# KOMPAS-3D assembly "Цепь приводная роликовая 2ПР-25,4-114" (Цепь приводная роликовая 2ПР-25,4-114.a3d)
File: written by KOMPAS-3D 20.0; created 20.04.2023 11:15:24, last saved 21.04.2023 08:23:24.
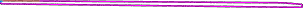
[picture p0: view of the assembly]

Document properties: Полное имя файла: C:\!WORK!\ЗИГ2-18.240.00 Линия ЗигЗаг\ЗИГ2-18.240.03.00 Цепь тяговая\Цепь приводная роликовая 2ПР-25,4-114.a3d

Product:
- Part/product: Цепь приводная роликовая 2ПР-25,4-114
    Масса: 114.772
    Раздел спецификации: Прочие изделия
  - Component [assembly]: Звено внутреннее двухрядное (25,4)  | qty 441  | pos. 627  | Масса: 0.150139; source file: ..\..\ЗИГ-18.240.00 Линия ЗигЗаг\Цепь\Звено внутренее двухрядное (25,4).a3d
  - Component [assembly]: Звено наружное двухрядное (25,4)  | qty 441  | pos. 520  | Масса: 0.110117; source file: ..\..\ЗИГ-18.240.00 Линия ЗигЗаг\Цепь\Звено наружное двухрядное (25,4).a3d

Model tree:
1. Эскиз:1
2. Массив вдоль кривой:1
3. Экземпляр ( 1 )
4. Экземпляр ( 2 )
5. Экземпляр ( 3 )
6. Экземпляр ( 4 )
7. Экземпляр ( 5 )
8. Экземпляр ( 6 )
9. Экземпляр ( 7 )
10. Экземпляр ( 8 )
11. Экземпляр ( 9 )
12. Экземпляр ( 10 )
13. Экземпляр ( 11 )
14. Экземпляр ( 12 )
15. Экземпляр ( 13 )
16. Экземпляр ( 14 )
17. Экземпляр ( 15 )
18. Экземпляр ( 16 )
19. Экземпляр ( 17 )
20. Экземпляр ( 18 )
21. Экземпляр ( 19 )
22. Экземпляр ( 20 )
23. Экземпляр ( 21 )
24. Экземпляр ( 22 )
25. Экземпляр ( 23 )
26. Экземпляр ( 24 )
27. Экземпляр ( 25 )
28. Экземпляр ( 26 )
29. Экземпляр ( 27 )
30. Экземпляр ( 28 )
31. Экземпляр ( 29 )
32. Экземпляр ( 30 )
33. Экземпляр ( 31 )
34. Экземпляр ( 32 )
35. Экземпляр ( 33 )
36. Экземпляр ( 34 )
37. Экземпляр ( 35 )
38. Экземпляр ( 36 )
39. Экземпляр ( 37 )
40. Экземпляр ( 38 )
41. Экземпляр ( 39 )
42. Экземпляр ( 40 )
43. Экземпляр ( 41 )
44. Экземпляр ( 42 )
45. Экземпляр ( 43 )
46. Экземпляр ( 44 )
47. Экземпляр ( 45 )
48. Экземпляр ( 46 )
49. Экземпляр ( 47 )
50. Экземпляр ( 48 )
51. Экземпляр ( 49 )
52. Экземпляр ( 50 )
53. Экземпляр ( 51 )
54. Экземпляр ( 52 )
55. Экземпляр ( 53 )
56. Экземпляр ( 54 )
57. Экземпляр ( 55 )
58. Экземпляр ( 56 )
59. Экземпляр ( 57 )
60. Экземпляр ( 58 )
61. Экземпляр ( 59 )
62. Экземпляр ( 60 )
63. Экземпляр ( 61 )
64. Экземпляр ( 62 )
65. Экземпляр ( 63 )
66. Экземпляр ( 64 )
67. Экземпляр ( 65 )
68. Экземпляр ( 66 )
69. Экземпляр ( 67 )
70. Экземпляр ( 68 )
71. Экземпляр ( 69 )
72. Экземпляр ( 70 )
73. Экземпляр ( 71 )
74. Экземпляр ( 72 )
75. Экземпляр ( 73 )
76. Экземпляр ( 74 )
77. Экземпляр ( 75 )
78. Экземпляр ( 76 )
79. Экземпляр ( 77 )
80. Экземпляр ( 78 )
81. Экземпляр ( 79 )
82. Экземпляр ( 80 )
83. Экземпляр ( 81 )
84. Экземпляр ( 82 )
85. Экземпляр ( 83 )
86. Экземпляр ( 84 )
87. Экземпляр ( 85 )
88. Экземпляр ( 86 )
89. Экземпляр ( 87 )
90. Экземпляр ( 88 )
91. Экземпляр ( 89 )
92. Экземпляр ( 90 )
93. Экземпляр ( 91 )
94. Экземпляр ( 92 )
95. Экземпляр ( 93 )
96. Экземпляр ( 94 )
97. Экземпляр ( 95 )
98. Экземпляр ( 96 )
99. Экземпляр ( 97 )
100. Экземпляр ( 98 )
101. Экземпляр ( 99 )
102. Экземпляр ( 100 )
103. Экземпляр ( 101 )
104. Экземпляр ( 102 )
105. Экземпляр ( 103 )
106. Экземпляр ( 104 )
107. Экземпляр ( 105 )
108. Экземпляр ( 106 )
109. Экземпляр ( 107 )
110. Экземпляр ( 108 )
111. Экземпляр ( 109 )
112. Экземпляр ( 110 )
113. Экземпляр ( 111 )
114. Экземпляр ( 112 )
115. Экземпляр ( 113 )
116. Экземпляр ( 114 )
117. Экземпляр ( 115 )
118. Экземпляр ( 116 )
119. Экземпляр ( 117 )
120. Экземпляр ( 118 )
121. Экземпляр ( 119 )
122. Экземпляр ( 120 )
123. Экземпляр ( 121 )
124. Экземпляр ( 122 )
125. Экземпляр ( 123 )
126. Экземпляр ( 124 )
127. Экземпляр ( 125 )
128. Экземпляр ( 126 )
129. Экземпляр ( 127 )
130. Экземпляр ( 128 )
131. Экземпляр ( 129 )
132. Экземпляр ( 130 )
133. Экземпляр ( 131 )
134. Экземпляр ( 132 )
135. Экземпляр ( 133 )
136. Экземпляр ( 134 )
137. Экземпляр ( 135 )
138. Экземпляр ( 136 )
139. Экземпляр ( 137 )
140. Экземпляр ( 138 )
141. Экземпляр ( 139 )
142. Экземпляр ( 140 )
143. Экземпляр ( 141 )
144. Экземпляр ( 142 )
145. Экземпляр ( 143 )
146. Экземпляр ( 144 )
147. Экземпляр ( 145 )
148. Экземпляр ( 146 )
149. Экземпляр ( 147 )
150. Экземпляр ( 148 )
151. Экземпляр ( 149 )
152. Экземпляр ( 150 )
153. Экземпляр ( 151 )
154. Экземпляр ( 152 )
155. Экземпляр ( 153 )
156. Экземпляр ( 154 )
157. Экземпляр ( 155 )
158. Экземпляр ( 156 )
159. Экземпляр ( 157 )
160. Экземпляр ( 158 )
161. Экземпляр ( 159 )
162. Экземпляр ( 160 )
163. Экземпляр ( 161 )
164. Экземпляр ( 162 )
165. Экземпляр ( 163 )
166. Экземпляр ( 164 )
167. Экземпляр ( 165 )
168. Экземпляр ( 166 )
169. Экземпляр ( 167 )
170. Экземпляр ( 168 )
171. Экземпляр ( 169 )
172. Экземпляр ( 170 )
173. Экземпляр ( 171 )
174. Экземпляр ( 172 )
175. Экземпляр ( 173 )
176. Экземпляр ( 174 )
177. Экземпляр ( 175 )
178. Экземпляр ( 176 )
179. Экземпляр ( 177 )
180. Экземпляр ( 178 )
181. Экземпляр ( 179 )
182. Экземпляр ( 180 )
183. Экземпляр ( 181 )
184. Экземпляр ( 182 )
185. Экземпляр ( 183 )
186. Экземпляр ( 184 )
187. Экземпляр ( 185 )
188. Экземпляр ( 186 )
189. Экземпляр ( 187 )
190. Экземпляр ( 188 )
191. Экземпляр ( 189 )
192. Экземпляр ( 190 )
193. Экземпляр ( 191 )
194. Экземпляр ( 192 )
195. Экземпляр ( 193 )
196. Экземпляр ( 194 )
197. Экземпляр ( 195 )
198. Экземпляр ( 196 )
199. Экземпляр ( 197 )
200. Экземпляр ( 198 )
201. Экземпляр ( 199 )
202. Экземпляр ( 200 )
203. Экземпляр ( 201 )
204. Экземпляр ( 202 )
205. Экземпляр ( 203 )
206. Экземпляр ( 204 )
207. Экземпляр ( 205 )
208. Экземпляр ( 206 )
209. Экземпляр ( 207 )
210. Экземпляр ( 208 )
211. Экземпляр ( 209 )
212. Экземпляр ( 210 )
213. Экземпляр ( 211 )
214. Экземпляр ( 212 )
215. Экземпляр ( 213 )
216. Экземпляр ( 214 )
217. Экземпляр ( 215 )
218. Экземпляр ( 216 )
219. Экземпляр ( 217 )
220. Экземпляр ( 218 )
221. Экземпляр ( 219 )
222. Экземпляр ( 220 )
223. Экземпляр ( 221 )
224. Экземпляр ( 222 )
225. Экземпляр ( 223 )
226. Экземпляр ( 224 )
227. Экземпляр ( 225 )
228. Экземпляр ( 226 )
229. Экземпляр ( 227 )
230. Экземпляр ( 228 )
231. Экземпляр ( 229 )
232. Экземпляр ( 230 )
233. Экземпляр ( 231 )
234. Экземпляр ( 232 )
235. Экземпляр ( 233 )
236. Экземпляр ( 234 )
237. Экземпляр ( 235 )
238. Экземпляр ( 236 )
239. Экземпляр ( 237 )
240. Экземпляр ( 238 )
241. Экземпляр ( 239 )
242. Экземпляр ( 240 )
243. Экземпляр ( 241 )
244. Экземпляр ( 242 )
245. Экземпляр ( 243 )
246. Экземпляр ( 244 )
247. Экземпляр ( 245 )
248. Экземпляр ( 246 )
249. Экземпляр ( 247 )
250. Экземпляр ( 248 )
251. Экземпляр ( 249 )
252. Экземпляр ( 250 )
253. Экземпляр ( 251 )
254. Экземпляр ( 252 )
255. Экземпляр ( 253 )
256. Экземпляр ( 254 )
257. Экземпляр ( 255 )
258. Экземпляр ( 256 )
259. Экземпляр ( 257 )
260. Экземпляр ( 258 )
261. Экземпляр ( 259 )
262. Экземпляр ( 260 )
263. Экземпляр ( 261 )
264. Экземпляр ( 262 )
265. Экземпляр ( 263 )
266. Экземпляр ( 264 )
267. Экземпляр ( 265 )
268. Экземпляр ( 266 )
269. Экземпляр ( 267 )
270. Экземпляр ( 268 )
271. Экземпляр ( 269 )
272. Экземпляр ( 270 )
273. Экземпляр ( 271 )
274. Экземпляр ( 272 )
275. Экземпляр ( 273 )
276. Экземпляр ( 274 )
277. Экземпляр ( 275 )
278. Экземпляр ( 276 )
279. Экземпляр ( 277 )
280. Экземпляр ( 278 )
281. Экземпляр ( 279 )
282. Экземпляр ( 280 )
283. Экземпляр ( 281 )
284. Экземпляр ( 282 )
285. Экземпляр ( 283 )
286. Экземпляр ( 284 )
287. Экземпляр ( 285 )
288. Экземпляр ( 286 )
289. Экземпляр ( 287 )
290. Экземпляр ( 288 )
291. Экземпляр ( 289 )
292. Экземпляр ( 290 )
293. Экземпляр ( 291 )
294. Экземпляр ( 292 )
295. Экземпляр ( 293 )
296. Экземпляр ( 294 )
297. Экземпляр ( 295 )
298. Экземпляр ( 296 )
299. Экземпляр ( 297 )
300. Экземпляр ( 298 )
301. Экземпляр ( 299 )
302. Экземпляр ( 300 )
303. Экземпляр ( 301 )
304. Экземпляр ( 302 )
305. Экземпляр ( 303 )
306. Экземпляр ( 304 )
307. Экземпляр ( 305 )
308. Экземпляр ( 306 )
309. Экземпляр ( 307 )
310. Экземпляр ( 308 )
311. Экземпляр ( 309 )
312. Экземпляр ( 310 )
313. Экземпляр ( 311 )
314. Экземпляр ( 312 )
315. Экземпляр ( 313 )
316. Экземпляр ( 314 )
317. Экземпляр ( 315 )
318. Экземпляр ( 316 )
319. Экземпляр ( 317 )
320. Экземпляр ( 318 )
321. Экземпляр ( 319 )
322. Экземпляр ( 320 )
323. Экземпляр ( 321 )
324. Экземпляр ( 322 )
325. Экземпляр ( 323 )
326. Экземпляр ( 324 )
327. Экземпляр ( 325 )
328. Экземпляр ( 326 )
329. Экземпляр ( 327 )
330. Экземпляр ( 328 )
331. Экземпляр ( 329 )
332. Экземпляр ( 330 )
333. Экземпляр ( 331 )
334. Экземпляр ( 332 )
335. Экземпляр ( 333 )
336. Экземпляр ( 334 )
337. Экземпляр ( 335 )
338. Экземпляр ( 336 )
339. Экземпляр ( 337 )
340. Экземпляр ( 338 )
341. Экземпляр ( 339 )
342. Экземпляр ( 340 )
343. Экземпляр ( 341 )
344. Экземпляр ( 342 )
345. Экземпляр ( 343 )
346. Экземпляр ( 344 )
347. Экземпляр ( 345 )
348. Экземпляр ( 346 )
349. Экземпляр ( 347 )
350. Экземпляр ( 348 )
351. Экземпляр ( 349 )
352. Экземпляр ( 350 )
353. Экземпляр ( 351 )
354. Экземпляр ( 352 )
355. Экземпляр ( 353 )
356. Экземпляр ( 354 )
357. Экземпляр ( 355 )
358. Экземпляр ( 356 )
359. Экземпляр ( 357 )
360. Экземпляр ( 358 )
361. Экземпляр ( 359 )
362. Экземпляр ( 360 )
363. Экземпляр ( 361 )
364. Экземпляр ( 362 )
365. Экземпляр ( 363 )
366. Экземпляр ( 364 )
367. Экземпляр ( 365 )
368. Экземпляр ( 366 )
369. Экземпляр ( 367 )
370. Экземпляр ( 368 )
371. Экземпляр ( 369 )
372. Экземпляр ( 370 )
373. Экземпляр ( 371 )
374. Экземпляр ( 372 )
375. Экземпляр ( 373 )
376. Экземпляр ( 374 )
377. Экземпляр ( 375 )
378. Экземпляр ( 376 )
379. Экземпляр ( 377 )
380. Экземпляр ( 378 )
381. Экземпляр ( 379 )
382. Экземпляр ( 380 )
383. Экземпляр ( 381 )
384. Экземпляр ( 382 )
385. Экземпляр ( 383 )
386. Экземпляр ( 384 )
387. Экземпляр ( 385 )
388. Экземпляр ( 386 )
389. Экземпляр ( 387 )
390. Экземпляр ( 388 )
391. Экземпляр ( 389 )
392. Экземпляр ( 390 )
393. Экземпляр ( 391 )
394. Экземпляр ( 392 )
395. Экземпляр ( 393 )
396. Экземпляр ( 394 )
397. Экземпляр ( 395 )
398. Экземпляр ( 396 )
399. Экземпляр ( 397 )
400. Экземпляр ( 398 )
401. Экземпляр ( 399 )
402. Экземпляр ( 400 )
403. Экземпляр ( 401 )
404. Экземпляр ( 402 )
405. Экземпляр ( 403 )
406. Экземпляр ( 404 )
407. Экземпляр ( 405 )
408. Экземпляр ( 406 )
409. Экземпляр ( 407 )
410. Экземпляр ( 408 )
411. Экземпляр ( 409 )
412. Экземпляр ( 410 )
413. Экземпляр ( 411 )
414. Экземпляр ( 412 )
415. Экземпляр ( 413 )
416. Экземпляр ( 414 )
417. Экземпляр ( 415 )
418. Экземпляр ( 416 )
419. Экземпляр ( 417 )
420. Экземпляр ( 418 )
421. Экземпляр ( 419 )
422. Экземпляр ( 420 )
423. Экземпляр ( 421 )
424. Экземпляр ( 422 )
425. Экземпляр ( 423 )
426. Экземпляр ( 424 )
427. Экземпляр ( 425 )
428. Экземпляр ( 426 )
429. Экземпляр ( 427 )
430. Экземпляр ( 428 )
431. Экземпляр ( 429 )
432. Экземпляр ( 430 )
433. Экземпляр ( 431 )
434. Экземпляр ( 432 )
435. Экземпляр ( 433 )
436. Экземпляр ( 434 )
437. Экземпляр ( 435 )
438. Экземпляр ( 436 )
439. Экземпляр ( 437 )
440. Экземпляр ( 438 )
441. Экземпляр ( 439 )
442. Экземпляр ( 440 )
443. Экземпляр ( 441 )
444. Ось через точку по направлению:1
445. Ось через точку по направлению:2
446. Ось через точку по направлению:3  (with: Элемент вращения:1, Элемент выдавливания:1)
     Расстояние = 0.4; Расстояние = 0.4

Expressions: t/(SIND(180/z1)); t/(SIND(180/z2)); t/(SIND(180/z3)); L12+(d2/2)*RAD(a2)+L23+(d3/2)*RAD(a3)+L31+(d1/2)*RAD(a3); N/t; m*2; t*2; CEIL(n/2); n0*t
Referenced files in C:\!WORK!\ЗИГ-18.240.00 Линия ЗигЗаг\Цепь\: Звено наружное двухрядное (25,4).a3d, Звено внутренее двухрядное (25,4).a3d
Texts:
  Различия исполнений по сборочному чертежу
  Груп. спецификация (вариант А) ГОСТ 2.113-75.
  SAPR-SVARKA-38 docBasicParam
  SAPR-SVARKA-38 docBodyParam
  SAPR-SVARKA-38 docWeldSignParam
  делит. диам. звездочки
  длина кривой (расчетная)
  число звеньев (расчетное)
  ЧИСЛО ЗВЕНЬЕВ ПРИНЯТОЕ
  ДЛИНА ЦЕПИ ПРИНЯТАЯ
  Звено внутреннее двухрядное (25,4) (1)
  Звено наружное двухрядное (25,4) (1)
  Звено внутреннее двухрядное (25,4) (2)
  Звено наружное двухрядное (25,4) (2)
  Звено внутреннее двухрядное (25,4) (3)
  Звено наружное двухрядное (25,4) (3)
  Звено внутреннее двухрядное (25,4) (4)
  Звено наружное двухрядное (25,4) (4)
  Звено внутреннее двухрядное (25,4) (5)
  Звено наружное двухрядное (25,4) (5)
  Звено внутреннее двухрядное (25,4) (6)
  Звено наружное двухрядное (25,4) (6)
  Звено внутреннее двухрядное (25,4) (7)
  Звено наружное двухрядное (25,4) (7)
  Звено внутреннее двухрядное (25,4) (8)
  Звено наружное двухрядное (25,4) (8)
  Звено внутреннее двухрядное (25,4) (9)
  Звено наружное двухрядное (25,4) (9)
  Звено внутреннее двухрядное (25,4) (10)
  Звено наружное двухрядное (25,4) (10)
  Звено внутреннее двухрядное (25,4) (11)
  Звено наружное двухрядное (25,4) (11)
  Звено внутреннее двухрядное (25,4) (12)
  Звено наружное двухрядное (25,4) (12)
  Звено внутреннее двухрядное (25,4) (13)
  Звено наружное двухрядное (25,4) (13)
  Звено внутреннее двухрядное (25,4) (14)
  Звено наружное двухрядное (25,4) (14)
  Звено внутреннее двухрядное (25,4) (15)
  Звено наружное двухрядное (25,4) (15)
  Звено внутреннее двухрядное (25,4) (16)
  Звено наружное двухрядное (25,4) (16)
  Звено внутреннее двухрядное (25,4) (17)
  Звено наружное двухрядное (25,4) (17)
  Звено внутреннее двухрядное (25,4) (18)
  Звено наружное двухрядное (25,4) (18)
  Звено внутреннее двухрядное (25,4) (19)
  Звено наружное двухрядное (25,4) (19)
  Звено внутреннее двухрядное (25,4) (20)
  Звено наружное двухрядное (25,4) (20)
  Звено внутреннее двухрядное (25,4) (21)
  Звено наружное двухрядное (25,4) (21)
  Звено внутреннее двухрядное (25,4) (22)
  Звено наружное двухрядное (25,4) (22)
  Звено внутреннее двухрядное (25,4) (23)
  Звено наружное двухрядное (25,4) (23)
  Звено внутреннее двухрядное (25,4) (24)
  Звено наружное двухрядное (25,4) (24)
  Звено внутреннее двухрядное (25,4) (25)
  Звено наружное двухрядное (25,4) (25)
  Звено внутреннее двухрядное (25,4) (26)
  Звено наружное двухрядное (25,4) (26)
  Звено внутреннее двухрядное (25,4) (27)
  Звено наружное двухрядное (25,4) (27)
  Звено внутреннее двухрядное (25,4) (28)
  Звено наружное двухрядное (25,4) (28)
  Звено внутреннее двухрядное (25,4) (29)
  Звено наружное двухрядное (25,4) (29)
  Звено внутреннее двухрядное (25,4) (30)
  Звено наружное двухрядное (25,4) (30)
  Звено внутреннее двухрядное (25,4) (31)
  Звено наружное двухрядное (25,4) (31)
  Звено внутреннее двухрядное (25,4) (32)
  Звено наружное двухрядное (25,4) (32)
  Звено внутреннее двухрядное (25,4) (33)
  Звено наружное двухрядное (25,4) (33)
  Звено внутреннее двухрядное (25,4) (34)
  Звено наружное двухрядное (25,4) (34)
  Звено внутреннее двухрядное (25,4) (35)
  Звено наружное двухрядное (25,4) (35)
  Звено внутреннее двухрядное (25,4) (36)
  Звено наружное двухрядное (25,4) (36)
  Звено внутреннее двухрядное (25,4) (37)
  Звено наружное двухрядное (25,4) (37)
  Звено внутреннее двухрядное (25,4) (38)
  Звено наружное двухрядное (25,4) (38)
  Звено внутреннее двухрядное (25,4) (39)
  Звено наружное двухрядное (25,4) (39)
  Звено внутреннее двухрядное (25,4) (40)
  Звено наружное двухрядное (25,4) (40)
  Звено внутреннее двухрядное (25,4) (41)
  Звено наружное двухрядное (25,4) (41)
  Звено внутреннее двухрядное (25,4) (42)
  Звено наружное двухрядное (25,4) (42)
  Звено внутреннее двухрядное (25,4) (43)
  Звено наружное двухрядное (25,4) (43)
  Звено внутреннее двухрядное (25,4) (44)
  Звено наружное двухрядное (25,4) (44)
  Звено внутреннее двухрядное (25,4) (45)
  Звено наружное двухрядное (25,4) (45)
  Звено внутреннее двухрядное (25,4) (46)
  Звено наружное двухрядное (25,4) (46)
  Звено внутреннее двухрядное (25,4) (47)
  Звено наружное двухрядное (25,4) (47)
  Звено внутреннее двухрядное (25,4) (48)
  Звено наружное двухрядное (25,4) (48)
  Звено внутреннее двухрядное (25,4) (49)
  Звено наружное двухрядное (25,4) (49)
  Звено внутреннее двухрядное (25,4) (50)
  Звено наружное двухрядное (25,4) (50)
  Звено внутреннее двухрядное (25,4) (51)
  Звено наружное двухрядное (25,4) (51)
  Звено внутреннее двухрядное (25,4) (52)
  Звено наружное двухрядное (25,4) (52)
  Звено внутреннее двухрядное (25,4) (53)
  Звено наружное двухрядное (25,4) (53)
  Звено внутреннее двухрядное (25,4) (54)
  Звено наружное двухрядное (25,4) (54)
  Звено внутреннее двухрядное (25,4) (55)
  Звено наружное двухрядное (25,4) (55)
  Звено внутреннее двухрядное (25,4) (56)
  Звено наружное двухрядное (25,4) (56)
  Звено внутреннее двухрядное (25,4) (57)
  Звено наружное двухрядное (25,4) (57)
  Звено внутреннее двухрядное (25,4) (58)
  Звено наружное двухрядное (25,4) (58)
  Звено внутреннее двухрядное (25,4) (59)
  Звено наружное двухрядное (25,4) (59)
  Звено внутреннее двухрядное (25,4) (60)
  Звено наружное двухрядное (25,4) (60)
  Звено внутреннее двухрядное (25,4) (61)
  Звено наружное двухрядное (25,4) (61)
  Звено внутреннее двухрядное (25,4) (62)
  Звено наружное двухрядное (25,4) (62)
  Звено внутреннее двухрядное (25,4) (63)
  Звено наружное двухрядное (25,4) (63)
  Звено внутреннее двухрядное (25,4) (64)
  Звено наружное двухрядное (25,4) (64)
  Звено внутреннее двухрядное (25,4) (65)
  Звено наружное двухрядное (25,4) (65)
  Звено внутреннее двухрядное (25,4) (66)
  Звено наружное двухрядное (25,4) (66)
  Звено внутреннее двухрядное (25,4) (67)
  Звено наружное двухрядное (25,4) (67)
  Звено внутреннее двухрядное (25,4) (68)
  Звено наружное двухрядное (25,4) (68)
  Звено внутреннее двухрядное (25,4) (69)
  Звено наружное двухрядное (25,4) (69)
  Звено внутреннее двухрядное (25,4) (70)
  Звено наружное двухрядное (25,4) (70)
  Звено внутреннее двухрядное (25,4) (71)
  Звено наружное двухрядное (25,4) (71)
  Звено внутреннее двухрядное (25,4) (72)
  Звено наружное двухрядное (25,4) (72)
  Звено внутреннее двухрядное (25,4) (73)
  Звено наружное двухрядное (25,4) (73)
  Звено внутреннее двухрядное (25,4) (74)
  Звено наружное двухрядное (25,4) (74)
  Звено внутреннее двухрядное (25,4) (75)
  Звено наружное двухрядное (25,4) (75)
  Звено внутреннее двухрядное (25,4) (76)
  Звено наружное двухрядное (25,4) (76)
  Звено внутреннее двухрядное (25,4) (77)
  Звено наружное двухрядное (25,4) (77)
  Звено внутреннее двухрядное (25,4) (78)
  Звено наружное двухрядное (25,4) (78)
  Звено внутреннее двухрядное (25,4) (79)
  Звено наружное двухрядное (25,4) (79)
  Звено внутреннее двухрядное (25,4) (80)
  Звено наружное двухрядное (25,4) (80)
  Звено внутреннее двухрядное (25,4) (81)
  Звено наружное двухрядное (25,4) (81)
  Звено внутреннее двухрядное (25,4) (82)
  Звено наружное двухрядное (25,4) (82)
  Звено внутреннее двухрядное (25,4) (83)
  Звено наружное двухрядное (25,4) (83)
  Звено внутреннее двухрядное (25,4) (84)
  Звено наружное двухрядное (25,4) (84)
  Звено внутреннее двухрядное (25,4) (85)
  Звено наружное двухрядное (25,4) (85)
  Звено внутреннее двухрядное (25,4) (86)
  Звено наружное двухрядное (25,4) (86)
  Звено внутреннее двухрядное (25,4) (87)
  Звено наружное двухрядное (25,4) (87)
  Звено внутреннее двухрядное (25,4) (88)
  Звено наружное двухрядное (25,4) (88)
  Звено внутреннее двухрядное (25,4) (89)
  Звено наружное двухрядное (25,4) (89)
  Звено внутреннее двухрядное (25,4) (90)
  Звено наружное двухрядное (25,4) (90)
  Звено внутреннее двухрядное (25,4) (91)
  Звено наружное двухрядное (25,4) (91)
  Звено внутреннее двухрядное (25,4) (92)
  Звено наружное двухрядное (25,4) (92)
  Звено внутреннее двухрядное (25,4) (93)
  Звено наружное двухрядное (25,4) (93)
  Звено внутреннее двухрядное (25,4) (94)
  Звено наружное двухрядное (25,4) (94)
  Звено внутреннее двухрядное (25,4) (95)
  Звено наружное двухрядное (25,4) (95)
  Звено внутреннее двухрядное (25,4) (96)
  Звено наружное двухрядное (25,4) (96)
  Звено внутреннее двухрядное (25,4) (97)
  Звено наружное двухрядное (25,4) (97)
  Звено внутреннее двухрядное (25,4) (98)
  Звено наружное двухрядное (25,4) (98)
  Звено внутреннее двухрядное (25,4) (99)
  Звено наружное двухрядное (25,4) (99)
  Звено внутреннее двухрядное (25,4) (100)
  Звено наружное двухрядное (25,4) (100)
  Звено внутреннее двухрядное (25,4) (101)
  Звено наружное двухрядное (25,4) (101)
  Звено внутреннее двухрядное (25,4) (102)
  Звено наружное двухрядное (25,4) (102)
  Звено внутреннее двухрядное (25,4) (103)
  Звено наружное двухрядное (25,4) (103)
  Звено внутреннее двухрядное (25,4) (104)
  Звено наружное двухрядное (25,4) (104)
  Звено внутреннее двухрядное (25,4) (105)
  Звено наружное двухрядное (25,4) (105)
  Звено внутреннее двухрядное (25,4) (106)
  Звено наружное двухрядное (25,4) (106)
  Звено внутреннее двухрядное (25,4) (107)
  Звено наружное двухрядное (25,4) (107)
  Звено внутреннее двухрядное (25,4) (108)
  Звено наружное двухрядное (25,4) (108)
  Звено внутреннее двухрядное (25,4) (109)
  Звено наружное двухрядное (25,4) (109)
  Звено внутреннее двухрядное (25,4) (110)
  Звено наружное двухрядное (25,4) (110)
  Звено внутреннее двухрядное (25,4) (111)
  Звено наружное двухрядное (25,4) (111)
  Звено внутреннее двухрядное (25,4) (112)
  Звено наружное двухрядное (25,4) (112)
  Звено внутреннее двухрядное (25,4) (113)
  Звено наружное двухрядное (25,4) (113)
  Звено внутреннее двухрядное (25,4) (114)
  Звено наружное двухрядное (25,4) (114)
  Звено внутреннее двухрядное (25,4) (115)
  Звено наружное двухрядное (25,4) (115)
  Звено внутреннее двухрядное (25,4) (116)
  Звено наружное двухрядное (25,4) (116)
  Звено внутреннее двухрядное (25,4) (117)
  Звено наружное двухрядное (25,4) (117)
  Звено внутреннее двухрядное (25,4) (118)
  Звено наружное двухрядное (25,4) (118)
  Звено внутреннее двухрядное (25,4) (119)
  Звено наружное двухрядное (25,4) (119)
  Звено внутреннее двухрядное (25,4) (120)
  Звено наружное двухрядное (25,4) (120)
  Звено внутреннее двухрядное (25,4) (121)
  Звено наружное двухрядное (25,4) (121)
  Звено внутреннее двухрядное (25,4) (122)
  Звено наружное двухрядное (25,4) (122)
  Звено внутреннее двухрядное (25,4) (123)
  Звено наружное двухрядное (25,4) (123)
  Звено внутреннее двухрядное (25,4) (124)
  Звено наружное двухрядное (25,4) (124)
  Звено внутреннее двухрядное (25,4) (125)
  Звено наружное двухрядное (25,4) (125)
  Звено внутреннее двухрядное (25,4) (126)
  Звено наружное двухрядное (25,4) (126)
  Звено внутреннее двухрядное (25,4) (127)
  Звено наружное двухрядное (25,4) (127)
  Звено внутреннее двухрядное (25,4) (128)
  Звено наружное двухрядное (25,4) (128)
  Звено внутреннее двухрядное (25,4) (129)
  Звено наружное двухрядное (25,4) (129)
  Звено внутреннее двухрядное (25,4) (130)
  Звено наружное двухрядное (25,4) (130)
  Звено внутреннее двухрядное (25,4) (131)
  Звено наружное двухрядное (25,4) (131)
  Звено внутреннее двухрядное (25,4) (132)
  Звено наружное двухрядное (25,4) (132)
  Звено внутреннее двухрядное (25,4) (133)
  Звено наружное двухрядное (25,4) (133)
  Звено внутреннее двухрядное (25,4) (134)
  Звено наружное двухрядное (25,4) (134)
  Звено внутреннее двухрядное (25,4) (135)
  Звено наружное двухрядное (25,4) (135)
  Звено внутреннее двухрядное (25,4) (136)
  Звено наружное двухрядное (25,4) (136)
  Звено внутреннее двухрядное (25,4) (137)
  Звено наружное двухрядное (25,4) (137)
  Звено внутреннее двухрядное (25,4) (138)
  Звено наружное двухрядное (25,4) (138)
  Звено внутреннее двухрядное (25,4) (139)
  Звено наружное двухрядное (25,4) (139)
  Звено внутреннее двухрядное (25,4) (140)
  Звено наружное двухрядное (25,4) (140)
  Звено внутреннее двухрядное (25,4) (141)
  Звено наружное двухрядное (25,4) (141)
  Звено внутреннее двухрядное (25,4) (142)
  Звено наружное двухрядное (25,4) (142)
  Звено внутреннее двухрядное (25,4) (143)
  Звено наружное двухрядное (25,4) (143)
  Звено внутреннее двухрядное (25,4) (144)
  Звено наружное двухрядное (25,4) (144)
  Звено внутреннее двухрядное (25,4) (145)
  Звено наружное двухрядное (25,4) (145)
  Звено внутреннее двухрядное (25,4) (146)
  Звено наружное двухрядное (25,4) (146)
  Звено внутреннее двухрядное (25,4) (147)
  Звено наружное двухрядное (25,4) (147)
  Звено внутреннее двухрядное (25,4) (148)
  Звено наружное двухрядное (25,4) (148)
  Звено внутреннее двухрядное (25,4) (149)
  Звено наружное двухрядное (25,4) (149)
  Звено внутреннее двухрядное (25,4) (150)
  Звено наружное двухрядное (25,4) (150)
  Звено внутреннее двухрядное (25,4) (151)
  Звено наружное двухрядное (25,4) (151)
  Звено внутреннее двухрядное (25,4) (152)
  Звено наружное двухрядное (25,4) (152)
  Звено внутреннее двухрядное (25,4) (153)
  Звено наружное двухрядное (25,4) (153)
  Звено внутреннее двухрядное (25,4) (154)
  Звено наружное двухрядное (25,4) (154)
  Звено внутреннее двухрядное (25,4) (155)
  Звено наружное двухрядное (25,4) (155)
  Звено внутреннее двухрядное (25,4) (156)
  Звено наружное двухрядное (25,4) (156)
  Звено внутреннее двухрядное (25,4) (157)
  Звено наружное двухрядное (25,4) (157)
  Звено внутреннее двухрядное (25,4) (158)
  Звено наружное двухрядное (25,4) (158)
  Звено внутреннее двухрядное (25,4) (159)
  Звено наружное двухрядное (25,4) (159)
  Звено внутреннее двухрядное (25,4) (160)
  Звено наружное двухрядное (25,4) (160)
  Звено внутреннее двухрядное (25,4) (161)
  Звено наружное двухрядное (25,4) (161)
  Звено внутреннее двухрядное (25,4) (162)
  Звено наружное двухрядное (25,4) (162)
  Звено внутреннее двухрядное (25,4) (163)
  Звено наружное двухрядное (25,4) (163)
  Звено внутреннее двухрядное (25,4) (164)
  Звено наружное двухрядное (25,4) (164)
  Звено внутреннее двухрядное (25,4) (165)
  Звено наружное двухрядное (25,4) (165)
  Звено внутреннее двухрядное (25,4) (166)
  Звено наружное двухрядное (25,4) (166)
  Звено внутреннее двухрядное (25,4) (167)
  Звено наружное двухрядное (25,4) (167)
  Звено внутреннее двухрядное (25,4) (168)
  Звено наружное двухрядное (25,4) (168)
  Звено внутреннее двухрядное (25,4) (169)
  Звено наружное двухрядное (25,4) (169)
  Звено внутреннее двухрядное (25,4) (170)
  Звено наружное двухрядное (25,4) (170)
  Звено внутреннее двухрядное (25,4) (171)
  Звено наружное двухрядное (25,4) (171)
  Звено внутреннее двухрядное (25,4) (172)
  Звено наружное двухрядное (25,4) (172)
  Звено внутреннее двухрядное (25,4) (173)
  Звено наружное двухрядное (25,4) (173)
  Звено внутреннее двухрядное (25,4) (174)
  Звено наружное двухрядное (25,4) (174)
  Звено внутреннее двухрядное (25,4) (175)
  Звено наружное двухрядное (25,4) (175)
  Звено внутреннее двухрядное (25,4) (176)
  Звено наружное двухрядное (25,4) (176)
  Звено внутреннее двухрядное (25,4) (177)
  Звено наружное двухрядное (25,4) (177)
  Звено внутреннее двухрядное (25,4) (178)
  Звено наружное двухрядное (25,4) (178)
  Звено внутреннее двухрядное (25,4) (179)
  Звено наружное двухрядное (25,4) (179)
  Звено внутреннее двухрядное (25,4) (180)
  Звено наружное двухрядное (25,4) (180)
  Звено внутреннее двухрядное (25,4) (181)
  Звено наружное двухрядное (25,4) (181)
  Звено внутреннее двухрядное (25,4) (182)
  Звено наружное двухрядное (25,4) (182)
  Звено внутреннее двухрядное (25,4) (183)
  Звено наружное двухрядное (25,4) (183)
  Звено внутреннее двухрядное (25,4) (184)
  Звено наружное двухрядное (25,4) (184)
  Звено внутреннее двухрядное (25,4) (185)
  Звено наружное двухрядное (25,4) (185)
  Звено внутреннее двухрядное (25,4) (186)
  Звено наружное двухрядное (25,4) (186)
  Звено внутреннее двухрядное (25,4) (187)
  Звено наружное двухрядное (25,4) (187)
  Звено внутреннее двухрядное (25,4) (188)
  Звено наружное двухрядное (25,4) (188)
  Звено внутреннее двухрядное (25,4) (189)
  Звено наружное двухрядное (25,4) (189)
  Звено внутреннее двухрядное (25,4) (190)
  Звено наружное двухрядное (25,4) (190)
  Звено внутреннее двухрядное (25,4) (191)
  Звено наружное двухрядное (25,4) (191)
  Звено внутреннее двухрядное (25,4) (192)
  Звено наружное двухрядное (25,4) (192)
  Звено внутреннее двухрядное (25,4) (193)
  Звено наружное двухрядное (25,4) (193)
  Звено внутреннее двухрядное (25,4) (194)
  Звено наружное двухрядное (25,4) (194)
  Звено внутреннее двухрядное (25,4) (195)
  Звено наружное двухрядное (25,4) (195)
  Звено внутреннее двухрядное (25,4) (196)
  Звено наружное двухрядное (25,4) (196)
  Звено внутреннее двухрядное (25,4) (197)
  Звено наружное двухрядное (25,4) (197)
  Звено внутреннее двухрядное (25,4) (198)
  Звено наружное двухрядное (25,4) (198)
  Звено внутреннее двухрядное (25,4) (199)
  Звено наружное двухрядное (25,4) (199)
  Звено внутреннее двухрядное (25,4) (200)
  Звено наружное двухрядное (25,4) (200)
  Звено внутреннее двухрядное (25,4) (201)
  Звено наружное двухрядное (25,4) (201)
  Звено внутреннее двухрядное (25,4) (202)
  Звено наружное двухрядное (25,4) (202)
  Звено внутреннее двухрядное (25,4) (203)
  Звено наружное двухрядное (25,4) (203)
  Звено внутреннее двухрядное (25,4) (204)
  Звено наружное двухрядное (25,4) (204)
  Звено внутреннее двухрядное (25,4) (205)
  Звено наружное двухрядное (25,4) (205)
  Звено внутреннее двухрядное (25,4) (206)
  Звено наружное двухрядное (25,4) (206)
  Звено внутреннее двухрядное (25,4) (207)
  Звено наружное двухрядное (25,4) (207)
  Звено внутреннее двухрядное (25,4) (208)
  Звено наружное двухрядное (25,4) (208)
  Звено внутреннее двухрядное (25,4) (209)
  Звено наружное двухрядное (25,4) (209)
  Звено внутреннее двухрядное (25,4) (210)
  Звено наружное двухрядное (25,4) (210)
  Звено внутреннее двухрядное (25,4) (211)
  Звено наружное двухрядное (25,4) (211)
  Звено внутреннее двухрядное (25,4) (212)
  Звено наружное двухрядное (25,4) (212)
  Звено внутреннее двухрядное (25,4) (213)
  Звено наружное двухрядное (25,4) (213)
  Звено внутреннее двухрядное (25,4) (214)
  Звено наружное двухрядное (25,4) (214)
  Звено внутреннее двухрядное (25,4) (215)
  Звено наружное двухрядное (25,4) (215)
  Звено внутреннее двухрядное (25,4) (216)
  Звено наружное двухрядное (25,4) (216)
  Звено внутреннее двухрядное (25,4) (217)
  Звено наружное двухрядное (25,4) (217)
  Звено внутреннее двухрядное (25,4) (218)
  Звено наружное двухрядное (25,4) (218)
  Звено внутреннее двухрядное (25,4) (219)
  Звено наружное двухрядное (25,4) (219)
  Звено внутреннее двухрядное (25,4) (220)
  Звено наружное двухрядное (25,4) (220)
  Звено внутреннее двухрядное (25,4) (221)
  Звено наружное двухрядное (25,4) (221)
  Звено внутреннее двухрядное (25,4) (222)
  Звено наружное двухрядное (25,4) (222)
  Звено внутреннее двухрядное (25,4) (223)
  Звено наружное двухрядное (25,4) (223)
  Звено внутреннее двухрядное (25,4) (224)
  Звено наружное двухрядное (25,4) (224)
  Звено внутреннее двухрядное (25,4) (225)
  Звено наружное двухрядное (25,4) (225)
  Звено внутреннее двухрядное (25,4) (226)
  Звено наружное двухрядное (25,4) (226)
  Звено внутреннее двухрядное (25,4) (227)
  Звено наружное двухрядное (25,4) (227)
  Звено внутреннее двухрядное (25,4) (228)
  Звено наружное двухрядное (25,4) (228)
  Звено внутреннее двухрядное (25,4) (229)
  Звено наружное двухрядное (25,4) (229)
  Звено внутреннее двухрядное (25,4) (230)
  Звено наружное двухрядное (25,4) (230)
  Звено внутреннее двухрядное (25,4) (231)
  Звено наружное двухрядное (25,4) (231)
  Звено внутреннее двухрядное (25,4) (232)
  Звено наружное двухрядное (25,4) (232)
  Звено внутреннее двухрядное (25,4) (233)
  Звено наружное двухрядное (25,4) (233)
  Звено внутреннее двухрядное (25,4) (234)
  Звено наружное двухрядное (25,4) (234)
  Звено внутреннее двухрядное (25,4) (235)
  Звено наружное двухрядное (25,4) (235)
  Звено внутреннее двухрядное (25,4) (236)
  Звено наружное двухрядное (25,4) (236)
  Звено внутреннее двухрядное (25,4) (237)
  Звено наружное двухрядное (25,4) (237)
  Звено внутреннее двухрядное (25,4) (238)
  Звено наружное двухрядное (25,4) (238)
  Звено внутреннее двухрядное (25,4) (239)
  Звено наружное двухрядное (25,4) (239)
  Звено внутреннее двухрядное (25,4) (240)
  Звено наружное двухрядное (25,4) (240)
  Звено внутреннее двухрядное (25,4) (241)
  Звено наружное двухрядное (25,4) (241)
  Звено внутреннее двухрядное (25,4) (242)
  Звено наружное двухрядное (25,4) (242)
  Звено внутреннее двухрядное (25,4) (243)
  Звено наружное двухрядное (25,4) (243)
  Звено внутреннее двухрядное (25,4) (244)
  Звено наружное двухрядное (25,4) (244)
  Звено внутреннее двухрядное (25,4) (245)
  Звено наружное двухрядное (25,4) (245)
  Звено внутреннее двухрядное (25,4) (246)
  Звено наружное двухрядное (25,4) (246)
  Звено внутреннее двухрядное (25,4) (247)
  Звено наружное двухрядное (25,4) (247)
  Звено внутреннее двухрядное (25,4) (248)
  Звено наружное двухрядное (25,4) (248)
  Звено внутреннее двухрядное (25,4) (249)
  Звено наружное двухрядное (25,4) (249)
  Звено внутреннее двухрядное (25,4) (250)
  Звено наружное двухрядное (25,4) (250)
  Звено внутреннее двухрядное (25,4) (251)
  Звено наружное двухрядное (25,4) (251)
  Звено внутреннее двухрядное (25,4) (252)
  Звено наружное двухрядное (25,4) (252)
  Звено внутреннее двухрядное (25,4) (253)
  Звено наружное двухрядное (25,4) (253)
  Звено внутреннее двухрядное (25,4) (254)
  Звено наружное двухрядное (25,4) (254)
  Звено внутреннее двухрядное (25,4) (255)
  Звено наружное двухрядное (25,4) (255)
  Звено внутреннее двухрядное (25,4) (256)
  Звено наружное двухрядное (25,4) (256)
  Звено внутреннее двухрядное (25,4) (257)
  Звено наружное двухрядное (25,4) (257)
  Звено внутреннее двухрядное (25,4) (258)
  Звено наружное двухрядное (25,4) (258)
  Звено внутреннее двухрядное (25,4) (259)
  Звено наружное двухрядное (25,4) (259)
  Звено внутреннее двухрядное (25,4) (260)
  Звено наружное двухрядное (25,4) (260)
  Звено внутреннее двухрядное (25,4) (261)
  Звено наружное двухрядное (25,4) (261)
  Звено внутреннее двухрядное (25,4) (262)
  Звено наружное двухрядное (25,4) (262)
  Звено внутреннее двухрядное (25,4) (263)
  Звено наружное двухрядное (25,4) (263)
  Звено внутреннее двухрядное (25,4) (264)
  Звено наружное двухрядное (25,4) (264)
  Звено внутреннее двухрядное (25,4) (265)
  Звено наружное двухрядное (25,4) (265)
  Звено внутреннее двухрядное (25,4) (266)
  Звено наружное двухрядное (25,4) (266)
  Звено внутреннее двухрядное (25,4) (267)
  Звено наружное двухрядное (25,4) (267)
  Звено внутреннее двухрядное (25,4) (268)
  Звено наружное двухрядное (25,4) (268)
  Звено внутреннее двухрядное (25,4) (269)
  Звено наружное двухрядное (25,4) (269)
  Звено внутреннее двухрядное (25,4) (270)
  Звено наружное двухрядное (25,4) (270)
  Звено внутреннее двухрядное (25,4) (271)
  Звено наружное двухрядное (25,4) (271)
  Звено внутреннее двухрядное (25,4) (272)
  Звено наружное двухрядное (25,4) (272)
  Звено внутреннее двухрядное (25,4) (273)
  Звено наружное двухрядное (25,4) (273)
  Звено внутреннее двухрядное (25,4) (274)
  Звено наружное двухрядное (25,4) (274)
  Звено внутреннее двухрядное (25,4) (275)
  Звено наружное двухрядное (25,4) (275)
  Звено внутреннее двухрядное (25,4) (276)
  Звено наружное двухрядное (25,4) (276)
  Звено внутреннее двухрядное (25,4) (277)
  Звено наружное двухрядное (25,4) (277)
  Звено внутреннее двухрядное (25,4) (278)
  Звено наружное двухрядное (25,4) (278)
  Звено внутреннее двухрядное (25,4) (279)
  Звено наружное двухрядное (25,4) (279)
  Звено внутреннее двухрядное (25,4) (280)
  Звено наружное двухрядное (25,4) (280)
  Звено внутреннее двухрядное (25,4) (281)
  Звено наружное двухрядное (25,4) (281)
  Звено внутреннее двухрядное (25,4) (282)
  Звено наружное двухрядное (25,4) (282)
  Звено внутреннее двухрядное (25,4) (283)
  Звено наружное двухрядное (25,4) (283)
  Звено внутреннее двухрядное (25,4) (284)
  Звено наружное двухрядное (25,4) (284)
  Звено внутреннее двухрядное (25,4) (285)
  Звено наружное двухрядное (25,4) (285)
  Звено внутреннее двухрядное (25,4) (286)
  Звено наружное двухрядное (25,4) (286)
  Звено внутреннее двухрядное (25,4) (287)
  Звено наружное двухрядное (25,4) (287)
  Звено внутреннее двухрядное (25,4) (288)
  Звено наружное двухрядное (25,4) (288)
  Звено внутреннее двухрядное (25,4) (289)
  Звено наружное двухрядное (25,4) (289)
  Звено внутреннее двухрядное (25,4) (290)
  Звено наружное двухрядное (25,4) (290)
  Звено внутреннее двухрядное (25,4) (291)
  Звено наружное двухрядное (25,4) (291)
  Звено внутреннее двухрядное (25,4) (292)
  Звено наружное двухрядное (25,4) (292)
  Звено внутреннее двухрядное (25,4) (293)
  Звено наружное двухрядное (25,4) (293)
  Звено внутреннее двухрядное (25,4) (294)
  Звено наружное двухрядное (25,4) (294)
  Звено внутреннее двухрядное (25,4) (295)
  Звено наружное двухрядное (25,4) (295)
  Звено внутреннее двухрядное (25,4) (296)
  Звено наружное двухрядное (25,4) (296)
  Звено внутреннее двухрядное (25,4) (297)
  Звено наружное двухрядное (25,4) (297)
  Звено внутреннее двухрядное (25,4) (298)
  Звено наружное двухрядное (25,4) (298)
  Звено внутреннее двухрядное (25,4) (299)
  Звено наружное двухрядное (25,4) (299)
  Звено внутреннее двухрядное (25,4) (300)
  Звено наружное двухрядное (25,4) (300)
  Звено внутреннее двухрядное (25,4) (301)
  Звено наружное двухрядное (25,4) (301)
  Звено внутреннее двухрядное (25,4) (302)
  Звено наружное двухрядное (25,4) (302)
  Звено внутреннее двухрядное (25,4) (303)
  Звено наружное двухрядное (25,4) (303)
  Звено внутреннее двухрядное (25,4) (304)
  Звено наружное двухрядное (25,4) (304)
  Звено внутреннее двухрядное (25,4) (305)
  Звено наружное двухрядное (25,4) (305)
  Звено внутреннее двухрядное (25,4) (306)
  Звено наружное двухрядное (25,4) (306)
  Звено внутреннее двухрядное (25,4) (307)
  Звено наружное двухрядное (25,4) (307)
  Звено внутреннее двухрядное (25,4) (308)
  Звено наружное двухрядное (25,4) (308)
  Звено внутреннее двухрядное (25,4) (309)
  Звено наружное двухрядное (25,4) (309)
  Звено внутреннее двухрядное (25,4) (310)
  Звено наружное двухрядное (25,4) (310)
  Звено внутреннее двухрядное (25,4) (311)
  Звено наружное двухрядное (25,4) (311)
  Звено внутреннее двухрядное (25,4) (312)
  Звено наружное двухрядное (25,4) (312)
  Звено внутреннее двухрядное (25,4) (313)
  Звено наружное двухрядное (25,4) (313)
  Звено внутреннее двухрядное (25,4) (314)
  Звено наружное двухрядное (25,4) (314)
  Звено внутреннее двухрядное (25,4) (315)
  Звено наружное двухрядное (25,4) (315)
  Звено внутреннее двухрядное (25,4) (316)
  Звено наружное двухрядное (25,4) (316)
  Звено внутреннее двухрядное (25,4) (317)
  Звено наружное двухрядное (25,4) (317)
  Звено внутреннее двухрядное (25,4) (318)
  Звено наружное двухрядное (25,4) (318)
  Звено внутреннее двухрядное (25,4) (319)
  Звено наружное двухрядное (25,4) (319)
  Звено внутреннее двухрядное (25,4) (320)
  Звено наружное двухрядное (25,4) (320)
  Звено внутреннее двухрядное (25,4) (321)
  Звено наружное двухрядное (25,4) (321)
  Звено внутреннее двухрядное (25,4) (322)
  Звено наружное двухрядное (25,4) (322)
  Звено внутреннее двухрядное (25,4) (323)
  Звено наружное двухрядное (25,4) (323)
  Звено внутреннее двухрядное (25,4) (324)
  Звено наружное двухрядное (25,4) (324)
  Звено внутреннее двухрядное (25,4) (325)
  Звено наружное двухрядное (25,4) (325)
  Звено внутреннее двухрядное (25,4) (326)
  Звено наружное двухрядное (25,4) (326)
  Звено внутреннее двухрядное (25,4) (327)
  Звено наружное двухрядное (25,4) (327)
  Звено внутреннее двухрядное (25,4) (328)
  Звено наружное двухрядное (25,4) (328)
  Звено внутреннее двухрядное (25,4) (329)
  Звено наружное двухрядное (25,4) (329)
  Звено внутреннее двухрядное (25,4) (330)
  Звено наружное двухрядное (25,4) (330)
  Звено внутреннее двухрядное (25,4) (331)
  Звено наружное двухрядное (25,4) (331)
  Звено внутреннее двухрядное (25,4) (332)
  Звено наружное двухрядное (25,4) (332)
  Звено внутреннее двухрядное (25,4) (333)
  Звено наружное двухрядное (25,4) (333)
  Звено внутреннее двухрядное (25,4) (334)
  Звено наружное двухрядное (25,4) (334)
  Звено внутреннее двухрядное (25,4) (335)
  Звено наружное двухрядное (25,4) (335)
  Звено внутреннее двухрядное (25,4) (336)
  Звено наружное двухрядное (25,4) (336)
  Звено внутреннее двухрядное (25,4) (337)
  Звено наружное двухрядное (25,4) (337)
  Звено внутреннее двухрядное (25,4) (338)
  Звено наружное двухрядное (25,4) (338)
  Звено внутреннее двухрядное (25,4) (339)
  Звено наружное двухрядное (25,4) (339)
  Звено внутреннее двухрядное (25,4) (340)
  Звено наружное двухрядное (25,4) (340)
  Звено внутреннее двухрядное (25,4) (341)
  Звено наружное двухрядное (25,4) (341)
  Звено внутреннее двухрядное (25,4) (342)
  Звено наружное двухрядное (25,4) (342)
  Звено внутреннее двухрядное (25,4) (343)
  Звено наружное двухрядное (25,4) (343)
  Звено внутреннее двухрядное (25,4) (344)
  Звено наружное двухрядное (25,4) (344)
  Звено внутреннее двухрядное (25,4) (345)
  Звено наружное двухрядное (25,4) (345)
  Звено внутреннее двухрядное (25,4) (346)
  Звено наружное двухрядное (25,4) (346)
  Звено внутреннее двухрядное (25,4) (347)
  Звено наружное двухрядное (25,4) (347)
  Звено внутреннее двухрядное (25,4) (348)
  Звено наружное двухрядное (25,4) (348)
  Звено внутреннее двухрядное (25,4) (349)
  Звено наружное двухрядное (25,4) (349)
  Звено внутреннее двухрядное (25,4) (350)
  Звено наружное двухрядное (25,4) (350)
  Звено внутреннее двухрядное (25,4) (351)
  Звено наружное двухрядное (25,4) (351)
  Звено внутреннее двухрядное (25,4) (352)
  Звено наружное двухрядное (25,4) (352)
  Звено внутреннее двухрядное (25,4) (353)
  Звено наружное двухрядное (25,4) (353)
  Звено внутреннее двухрядное (25,4) (354)
  Звено наружное двухрядное (25,4) (354)
  Звено внутреннее двухрядное (25,4) (355)
  Звено наружное двухрядное (25,4) (355)
  Звено внутреннее двухрядное (25,4) (356)
  Звено наружное двухрядное (25,4) (356)
  Звено внутреннее двухрядное (25,4) (357)
  Звено наружное двухрядное (25,4) (357)
  Звено внутреннее двухрядное (25,4) (358)
  Звено наружное двухрядное (25,4) (358)
  Звено внутреннее двухрядное (25,4) (359)
  Звено наружное двухрядное (25,4) (359)
  Звено внутреннее двухрядное (25,4) (360)
  Звено наружное двухрядное (25,4) (360)
  Звено внутреннее двухрядное (25,4) (361)
  Звено наружное двухрядное (25,4) (361)
  Звено внутреннее двухрядное (25,4) (362)
  Звено наружное двухрядное (25,4) (362)
  Звено внутреннее двухрядное (25,4) (363)
  Звено наружное двухрядное (25,4) (363)
  Звено внутреннее двухрядное (25,4) (364)
  Звено наружное двухрядное (25,4) (364)
  Звено внутреннее двухрядное (25,4) (365)
  Звено наружное двухрядное (25,4) (365)
  Звено внутреннее двухрядное (25,4) (366)
  Звено наружное двухрядное (25,4) (366)
  Звено внутреннее двухрядное (25,4) (367)
  Звено наружное двухрядное (25,4) (367)
  Звено внутреннее двухрядное (25,4) (368)
  Звено наружное двухрядное (25,4) (368)
  Звено внутреннее двухрядное (25,4) (369)
  Звено наружное двухрядное (25,4) (369)
  Звено внутреннее двухрядное (25,4) (370)
  Звено наружное двухрядное (25,4) (370)
  Звено внутреннее двухрядное (25,4) (371)
  Звено наружное двухрядное (25,4) (371)
  Звено внутреннее двухрядное (25,4) (372)
  Звено наружное двухрядное (25,4) (372)
  Звено внутреннее двухрядное (25,4) (373)
  Звено наружное двухрядное (25,4) (373)
  Звено внутреннее двухрядное (25,4) (374)
  Звено наружное двухрядное (25,4) (374)
  Звено внутреннее двухрядное (25,4) (375)
  Звено наружное двухрядное (25,4) (375)
  Звено внутреннее двухрядное (25,4) (376)
  Звено наружное двухрядное (25,4) (376)
  Звено внутреннее двухрядное (25,4) (377)
  Звено наружное двухрядное (25,4) (377)
  Звено внутреннее двухрядное (25,4) (378)
  Звено наружное двухрядное (25,4) (378)
  Звено внутреннее двухрядное (25,4) (379)
  Звено наружное двухрядное (25,4) (379)
  Звено внутреннее двухрядное (25,4) (380)
  Звено наружное двухрядное (25,4) (380)
  Звено внутреннее двухрядное (25,4) (381)
  Звено наружное двухрядное (25,4) (381)
  Звено внутреннее двухрядное (25,4) (382)
  Звено наружное двухрядное (25,4) (382)
  Звено внутреннее двухрядное (25,4) (383)
  Звено наружное двухрядное (25,4) (383)
  Звено внутреннее двухрядное (25,4) (384)
  Звено наружное двухрядное (25,4) (384)
  Звено внутреннее двухрядное (25,4) (385)
  Звено наружное двухрядное (25,4) (385)
  Звено внутреннее двухрядное (25,4) (386)
  Звено наружное двухрядное (25,4) (386)
  Звено внутреннее двухрядное (25,4) (387)
  Звено наружное двухрядное (25,4) (387)
  Звено внутреннее двухрядное (25,4) (388)
  Звено наружное двухрядное (25,4) (388)
  Звено внутреннее двухрядное (25,4) (389)
  Звено наружное двухрядное (25,4) (389)
  Звено внутреннее двухрядное (25,4) (390)
  Звено наружное двухрядное (25,4) (390)
  Звено внутреннее двухрядное (25,4) (391)
  Звено наружное двухрядное (25,4) (391)
  Звено внутреннее двухрядное (25,4) (392)
  Звено наружное двухрядное (25,4) (392)
  Звено внутреннее двухрядное (25,4) (393)
  Звено наружное двухрядное (25,4) (393)
  Звено внутреннее двухрядное (25,4) (394)
  Звено наружное двухрядное (25,4) (394)
  Звено внутреннее двухрядное (25,4) (395)
  Звено наружное двухрядное (25,4) (395)
  Звено внутреннее двухрядное (25,4) (396)
  Звено наружное двухрядное (25,4) (396)
  Звено внутреннее двухрядное (25,4) (397)
  Звено наружное двухрядное (25,4) (397)
  Звено внутреннее двухрядное (25,4) (398)
  Звено наружное двухрядное (25,4) (398)
  Звено внутреннее двухрядное (25,4) (399)
  Звено наружное двухрядное (25,4) (399)
  Звено внутреннее двухрядное (25,4) (400)
  Звено наружное двухрядное (25,4) (400)
  Звено внутреннее двухрядное (25,4) (401)
  Звено наружное двухрядное (25,4) (401)
  Звено внутреннее двухрядное (25,4) (402)
  Звено наружное двухрядное (25,4) (402)
  Звено внутреннее двухрядное (25,4) (403)
  Звено наружное двухрядное (25,4) (403)
  Звено внутреннее двухрядное (25,4) (404)
  Звено наружное двухрядное (25,4) (404)
  Звено внутреннее двухрядное (25,4) (405)
  Звено наружное двухрядное (25,4) (405)
  Звено внутреннее двухрядное (25,4) (406)
  Звено наружное двухрядное (25,4) (406)
  Звено внутреннее двухрядное (25,4) (407)
  Звено наружное двухрядное (25,4) (407)
  Звено внутреннее двухрядное (25,4) (408)
  Звено наружное двухрядное (25,4) (408)
  Звено внутреннее двухрядное (25,4) (409)
  Звено наружное двухрядное (25,4) (409)
  Звено внутреннее двухрядное (25,4) (410)
  Звено наружное двухрядное (25,4) (410)
  Звено внутреннее двухрядное (25,4) (411)
  Звено наружное двухрядное (25,4) (411)
  Звено внутреннее двухрядное (25,4) (412)
  Звено наружное двухрядное (25,4) (412)
  Звено внутреннее двухрядное (25,4) (413)
  Звено наружное двухрядное (25,4) (413)
  Звено внутреннее двухрядное (25,4) (414)
  Звено наружное двухрядное (25,4) (414)
  Звено внутреннее двухрядное (25,4) (415)
  Звено наружное двухрядное (25,4) (415)
  Звено внутреннее двухрядное (25,4) (416)
  Звено наружное двухрядное (25,4) (416)
  Звено внутреннее двухрядное (25,4) (417)
  Звено наружное двухрядное (25,4) (417)
  Звено внутреннее двухрядное (25,4) (418)
  Звено наружное двухрядное (25,4) (418)
  Звено внутреннее двухрядное (25,4) (419)
  Звено наружное двухрядное (25,4) (419)
  Звено внутреннее двухрядное (25,4) (420)
  Звено наружное двухрядное (25,4) (420)
  Звено внутреннее двухрядное (25,4) (421)
  Звено наружное двухрядное (25,4) (421)
  Звено внутреннее двухрядное (25,4) (422)
  Звено наружное двухрядное (25,4) (422)
  Звено внутреннее двухрядное (25,4) (423)
  Звено наружное двухрядное (25,4) (423)
  Звено внутреннее двухрядное (25,4) (424)
  Звено наружное двухрядное (25,4) (424)
  Звено внутреннее двухрядное (25,4) (425)
  Звено наружное двухрядное (25,4) (425)
  Звено внутреннее двухрядное (25,4) (426)
  Звено наружное двухрядное (25,4) (426)
  Звено внутреннее двухрядное (25,4) (427)
  Звено наружное двухрядное (25,4) (427)
  Звено внутреннее двухрядное (25,4) (428)
  Звено наружное двухрядное (25,4) (428)
  Звено внутреннее двухрядное (25,4) (429)
  Звено наружное двухрядное (25,4) (429)
  Звено внутреннее двухрядное (25,4) (430)
  Звено наружное двухрядное (25,4) (430)
  Звено внутреннее двухрядное (25,4) (431)
  Звено наружное двухрядное (25,4) (431)
  Звено внутреннее двухрядное (25,4) (432)
  Звено наружное двухрядное (25,4) (432)
  Звено внутреннее двухрядное (25,4) (433)
  Звено наружное двухрядное (25,4) (433)
  Звено внутреннее двухрядное (25,4) (434)
  Звено наружное двухрядное (25,4) (434)
  Звено внутреннее двухрядное (25,4) (435)
  Звено наружное двухрядное (25,4) (435)
  Звено внутреннее двухрядное (25,4) (436)
  Звено наружное двухрядное (25,4) (436)
  Звено внутреннее двухрядное (25,4) (437)
  Звено наружное двухрядное (25,4) (437)
  Звено внутреннее двухрядное (25,4) (438)
  Звено наружное двухрядное (25,4) (438)
  Звено внутреннее двухрядное (25,4) (439)
  Звено наружное двухрядное (25,4) (439)
  Звено внутреннее двухрядное (25,4) (440)
  Звено наружное двухрядное (25,4) (440)
  Звено внутреннее двухрядное (25,4) (441)
  Звено наружное двухрядное (25,4) (441)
